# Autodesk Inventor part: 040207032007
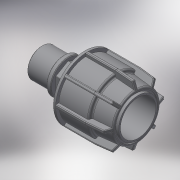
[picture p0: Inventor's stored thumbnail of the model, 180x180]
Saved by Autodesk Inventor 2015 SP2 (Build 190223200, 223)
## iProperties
Created: 2017-08
Part Number: 040207032007
Material: Generic
Description: PLASSON IRRIFIT ADAPTOR 32-3/4"M
Document SubType Name: Modeling
Designer: KIM
Density: 1 g/cm^3
Appearance: Default
Author: KIM
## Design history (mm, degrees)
derived "040207.ipt"
feature "Solid1::040207.ipt"
tag "TaggingFeature1"
body "Solid1"
other parameters: "d5" = 48, "d6" = 18.7, "d10" = 57, "d22" = 20.955, "d24" = 1.955, "d25" = 51.3, "d26" = 45.6, "d31" = 1.28, "d49" = 2.85, "d50" = 0, "d58" = 0.64, "d61" = 360 deg, "d77" = 32, "d78" = 5 deg, "d80" = 35.2, "d81" = 42.5, "d82" = 2.55, "d84" = 5 deg, "d85" = 70 deg, "d86" = 54.15, "d87" = 0.425, "d88" = 0, "d89" = 48.45, "d90" = 4.25, "d91" = 0, "d99" = 20.955, "d100" = 17, "d101" = 3.4, "d102" = 85, "d103" = 25.146, "d104" = 0.4191, "d108" = 0, "d109" = 0.20955, "d112" = 16.764, "d113" = 38.4, "d_" = 32, "E_" = 57, "H_" = 85, "l_nut" = 48, "l_" = 17, "R_" = 20.955
